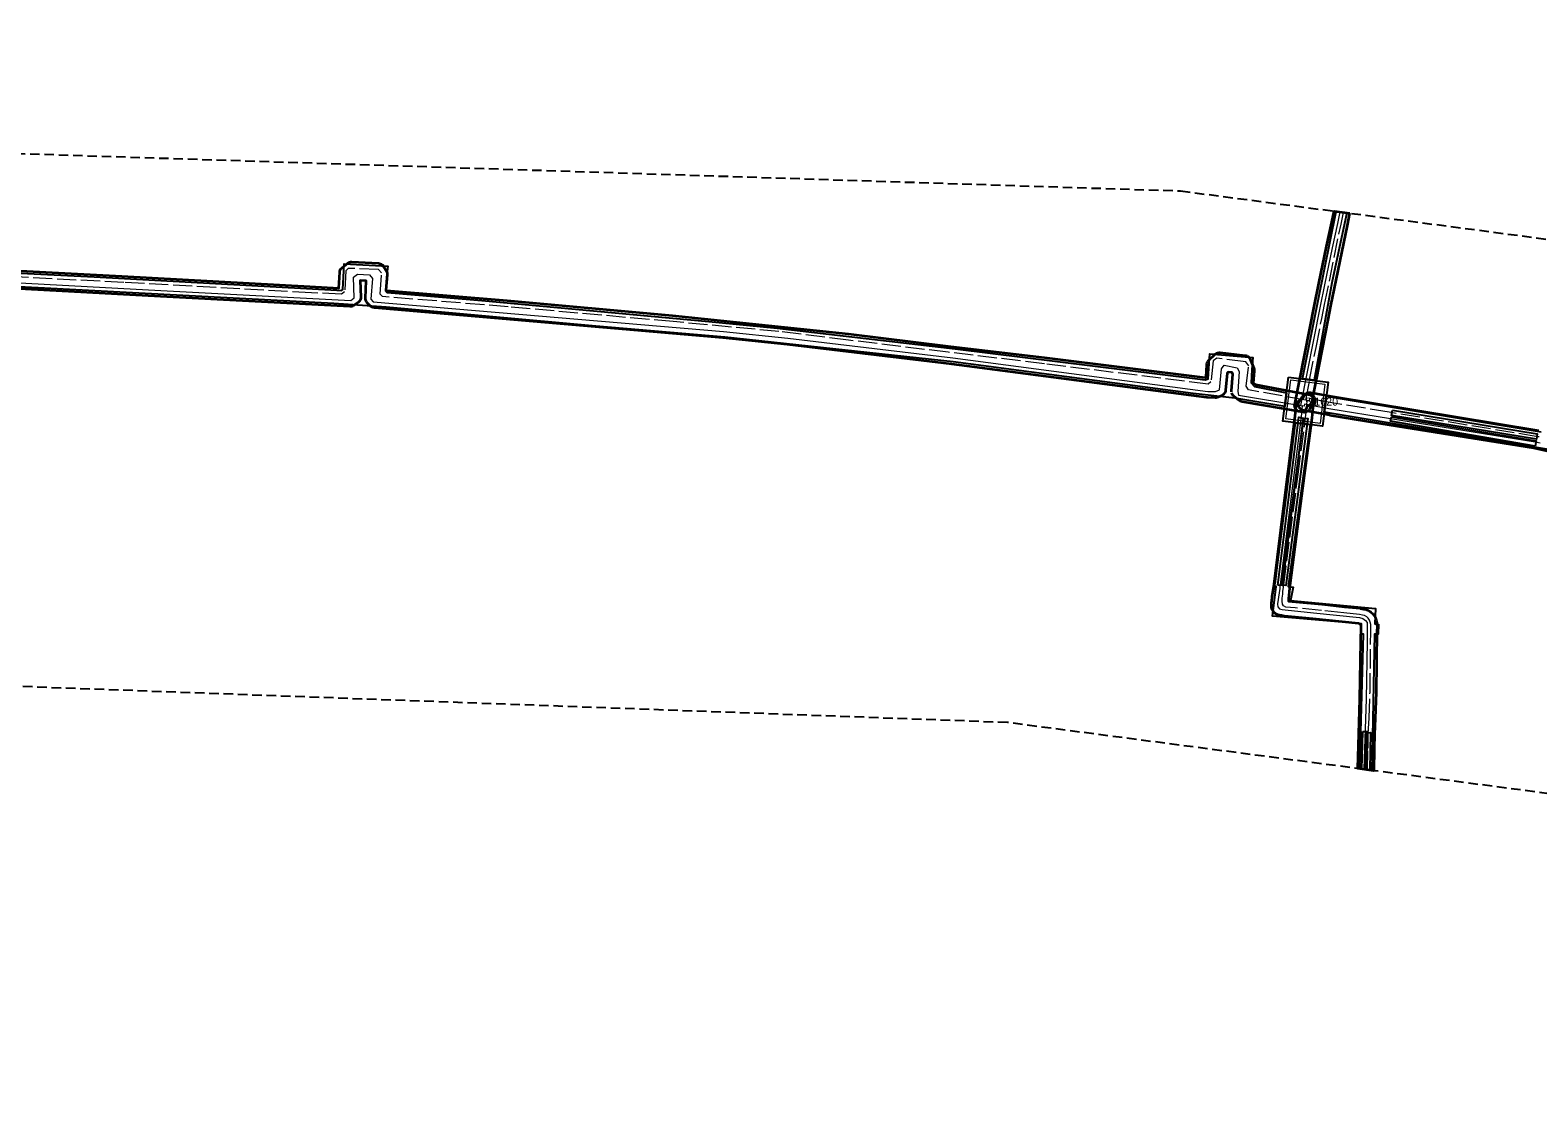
# Model space of a CAD drawing. Extents: x -451331 to -449998, y -1101254 to -1101132.
# Drawn here: x -450896.6 to -450726.4, y -1101253.5 to -1101132.1 of the extents above; entities that cross this region are included whole.
import ezdxf

# ---------------------------------------------------------------- set-up
doc = ezdxf.new("R2010")
doc.units = 0
doc.header["$LTSCALE"] = 0.36
doc.linetypes.add('LONG_DASHED', pattern=[7.5, 6, -1.5])
doc.linetypes.add('MEDIUM_DASHED', pattern=[4.5, 3, -1.5])
for name, color, linetype, lineweight in [('2', 7, 'Continuous', 13), ('3', 7, 'Continuous', 25), ('62', 7, 'MEDIUM_DASHED', 25), ('8', 7, 'Continuous', 35)]:
    doc.layers.add(name, color=color, linetype=linetype, lineweight=lineweight)

msp = doc.modelspace()

# ---------------------------------------------------------------- linework, layer by layer
at = {"layer": '2'}
for p, q in [((-450753.15, -1101174.471), (-450752.998, -1101174.497)), ((-450752.998, -1101174.497), (-450753.031, -1101174.872))]:
    msp.add_line(p, q, dxfattribs=at)
at = {"layer": '2', "linetype": 'LONG_DASHED'}
for p, q in [((-450752.423, -1101173.895), (-450752.592, -1101173.863)), ((-450752.525, -1101174.935), (-450752.423, -1101173.895))]:
    msp.add_line(p, q, dxfattribs=at)
at = {"layer": '2'}
for points in [[(-450753.15, -1101174.471), (-450750.934, -1101163.236), (-450750.445, -1101160.824), (-450749.565, -1101156.672), (-450748.981, -1101153.912), (-450748.706, -1101152.614)], [(-450924.057, -1101159.279), (-450903.363, -1101160.303), (-450881.853, -1101161.467), (-450860.382, -1101162.6), (-450860.033, -1101162.303), (-450860.078, -1101159.959), (-450859.628, -1101159.641), (-450858.305, -1101159.721), (-450857.961, -1101160.144), (-450858.14, -1101162.461), (-450857.872, -1101162.774), (-450818.326, -1101166.124), (-450811.077, -1101166.864), (-450792.45, -1101169.087), (-450763.663, -1101172.871), (-450762.79, -1101172.897), (-450762.34, -1101172.685), (-450762.092, -1101170.332), (-450761.805, -1101169.929), (-450760.353, -1101170.217), (-450760.111, -1101170.64), (-450760.277, -1101172.871), (-450760.195, -1101173.307), (-450753.15, -1101174.471)], [(-450751.662, -1101174.525), (-450752.719, -1101174.326), (-450752.759, -1101174.538), (-450752.998, -1101174.497)], [(-450743.258, -1101175.937), (-450749.764, -1101174.882), (-450751.662, -1101174.525)], [(-450753.031, -1101174.872), (-450753.109, -1101175.739), (-450754.306, -1101185.283), (-450755.523, -1101195.021), (-450755.539, -1101195.131)], [(-450726.139, -1101178.724), (-450726.711, -1101178.593), (-450743.025, -1101175.975), (-450743.258, -1101175.937)], [(-450755.539, -1101195.131), (-450755.676, -1101196.103), (-450755.747, -1101196.64), (-450755.77, -1101196.828), (-450755.779, -1101196.904), (-450755.75, -1101197.206), (-450755.564, -1101197.401), (-450755.252, -1101197.482), (-450754.92, -1101197.53), (-450751.724, -1101197.847), (-450746.515, -1101198.388), (-450746.149, -1101198.489), (-450745.85, -1101198.719), (-450745.679, -1101198.974), (-450745.652, -1101199.342), (-450745.665, -1101201.104), (-450745.793, -1101207.618), (-450746.031, -1101215.475), (-450746.033, -1101215.534)]]:
    msp.add_lwpolyline(points, dxfattribs=at)
at = {"layer": '2', "linetype": 'LONG_DASHED'}
for points in [[(-450752.592, -1101173.863), (-450752.159, -1101171.57), (-450751.439, -1101167.92), (-450750.79, -1101164.651), (-450750.475, -1101163.06), (-450748.616, -1101153.991), (-450748.342, -1101152.662)], [(-450752.592, -1101173.863), (-450759.07, -1101172.694), (-450759.306, -1101172.278), (-450759.032, -1101169.987), (-450759.348, -1101169.53), (-450762.651, -1101169.124), (-450763.042, -1101169.404), (-450763.299, -1101171.785), (-450763.608, -1101172.059), (-450782.098, -1101169.752), (-450792.952, -1101168.457), (-450804.201, -1101167.083), (-450812.061, -1101166.116), (-450824.006, -1101164.996), (-450842.623, -1101163.331), (-450856.817, -1101162.159), (-450857.095, -1101161.912), (-450856.925, -1101159.487), (-450857.263, -1101159.122), (-450860.682, -1101158.982), (-450860.942, -1101159.256), (-450861.094, -1101161.634), (-450861.434, -1101161.878), (-450864.831, -1101161.745), (-450886.009, -1101160.581), (-450908.217, -1101159.417)], [(-450751.502, -1101173.81), (-450752.176, -1101173.684), (-450752.222, -1101173.932), (-450752.423, -1101173.895)], [(-450743.19, -1101175.218), (-450749.661, -1101174.151), (-450751.502, -1101173.81)], [(-450755.2, -1101195.751), (-450755.166, -1101195.429), (-450755.119, -1101194.989), (-450755.104, -1101194.887), (-450755.085, -1101194.714), (-450754.355, -1101189.171), (-450753.46, -1101182.262), (-450752.609, -1101175.8), (-450752.525, -1101174.935)], [(-450726.252, -1101177.991), (-450726.397, -1101177.987), (-450743.19, -1101175.218)], [(-450745.615, -1101215.589), (-450745.566, -1101213.148), (-450745.534, -1101211.568), (-450745.455, -1101209.718), (-450745.338, -1101206.831), (-450745.252, -1101199.929), (-450745.251, -1101199.439), (-450745.259, -1101199.171), (-450745.311, -1101198.905), (-450745.389, -1101198.681), (-450745.549, -1101198.469), (-450745.714, -1101198.317), (-450745.957, -1101198.177), (-450746.175, -1101198.12), (-450746.539, -1101198.05), (-450748.287, -1101197.867), (-450750.83, -1101197.601), (-450753.794, -1101197.316), (-450754.862, -1101197.22), (-450755.111, -1101197.087), (-450755.227, -1101196.903), (-450755.259, -1101196.552), (-450755.25, -1101196.219), (-450755.2, -1101195.751)]]:
    msp.add_lwpolyline(points, dxfattribs=at)
at = {"layer": '3'}
for points in [[(-450747.966, -1101152.711), (-450748.225, -1101153.935), (-450749.637, -1101160.606), (-450751.632, -1101171.619), (-450752.975, -1101171.449), (-450751.159, -1101162.425), (-450749.178, -1101152.551)], [(-450754.549, -1101171.254), (-450750.083, -1101171.813), (-450750.706, -1101176.787), (-450755.173, -1101176.227)], [(-450744.38, -1101199.152), (-450744.409, -1101200.265), (-450744.853, -1101200.289), (-450745.146, -1101215.65), (-450746.492, -1101215.474), (-450746.079, -1101200.26), (-450746.364, -1101200.26), (-450746.32, -1101199.109), (-450756.345, -1101198.25), (-450755.95, -1101194.879), (-450756.109, -1101194.839), (-450756.014, -1101194.327), (-450755.778, -1101192.463), (-450754.85, -1101185.134), (-450753.744, -1101176.406), (-450752.112, -1101176.611), (-450754.586, -1101194.911), (-450754, -1101194.969), (-450754.301, -1101196.49), (-450744.719, -1101197.359), (-450744.799, -1101199.091)], [(-450755.739, -1101194.731), (-450753.371, -1101175.798), (-450752.873, -1101175.874), (-450755.25, -1101194.789)], [(-450752.814, -1101175.879), (-450752.375, -1101175.945), (-450754.839, -1101194.772), (-450755.34, -1101194.719)], [(-450742.933, -1101175.755), (-450726.603, -1101178.438), (-450726.683, -1101179.04), (-450743.012, -1101176.236)], [(-450742.812, -1101174.995), (-450726.461, -1101177.654), (-450726.559, -1101178.259), (-450742.91, -1101175.6)], [(-450746.15, -1101211.252), (-450745.65, -1101211.258), (-450745.782, -1101215.567), (-450746.28, -1101215.502)], [(-450745.863, -1101215.556), (-450745.78, -1101211.403), (-450745.28, -1101211.383), (-450745.365, -1101215.622)]]:
    msp.add_lwpolyline(points, close=True, dxfattribs=at)
for points in [[(-450920.932, -1101158.346), (-450889.362, -1101159.955), (-450861.956, -1101161.444), (-450861.45, -1101161.471), (-450861.284, -1101161.373), (-450861.177, -1101159.248), (-450861.151, -1101158.461), (-450856.236, -1101158.719), (-450856.316, -1101159.584), (-450856.482, -1101161.485), (-450856.287, -1101161.707), (-450845.59, -1101162.629), (-450819.971, -1101164.969), (-450812.261, -1101165.721), (-450792.175, -1101168.053), (-450765.116, -1101171.407), (-450763.968, -1101171.55), (-450763.613, -1101171.436), (-450763.501, -1101169.732), (-450763.41, -1101168.617), (-450758.56, -1101169.061), (-450758.668, -1101170.383), (-450758.673, -1101170.45), (-450758.769, -1101171.907), (-450758.374, -1101172.311), (-450754.772, -1101173.03), (-450754.966, -1101174.575), (-450760.596, -1101173.648), (-450765.31, -1101173.108), (-450792.408, -1101169.546), (-450818.178, -1101166.758), (-450832.744, -1101165.501), (-450856.404, -1101163.358), (-450862.309, -1101162.958), (-450895.688, -1101161.169), (-450923.154, -1101159.774)], [(-450724.513, -1101179.55), (-450750.507, -1101175.197), (-450750.285, -1101173.424), (-450726.039, -1101177.429)]]:
    msp.add_lwpolyline(points, dxfattribs=at)
at = {"layer": '3', "lineweight": 13}
msp.add_lwpolyline([(-450754.284, -1101171.573), (-450750.442, -1101172.049), (-450750.974, -1101176.494), (-450754.839, -1101175.97)], close=True, dxfattribs=at)
at = {"layer": '62'}
msp.add_lwpolyline([(-450786.261, -1101210.25), (-451322.174, -1101190.711), (-451330.547, -1101132.096), (-450766.722, -1101150.239), (-450459.689, -1101190.711), (-449997.743, -1101194.898), (-449997.743, -1101249.327), (-450456.897, -1101253.514)], close=True, dxfattribs=at)
at = {"layer": '8'}
msp.add_lwpolyline([(-450747.646, -1101152.753), (-450747.93, -1101154.132), (-450749.788, -1101163.199), (-450750.104, -1101164.787), (-450750.752, -1101168.056), (-450751.472, -1101171.702), (-450751.904, -1101173.993), (-450751.936, -1101174.107), (-450751.986, -1101174.214), (-450752.054, -1101174.311), (-450752.137, -1101174.395), (-450752.232, -1101174.464), (-450752.338, -1101174.516), (-450752.452, -1101174.549), (-450752.463, -1101174.606), (-450752.497, -1101174.723), (-450752.551, -1101174.833), (-450752.623, -1101174.931), (-450752.711, -1101175.016), (-450752.812, -1101175.084), (-450752.924, -1101175.133), (-450753.042, -1101175.162), (-450753.164, -1101175.171), (-450753.285, -1101175.157), (-450753.402, -1101175.123), (-450753.512, -1101175.07), (-450753.61, -1101174.998), (-450753.695, -1101174.91), (-450753.763, -1101174.808), (-450753.812, -1101174.697), (-450753.841, -1101174.578), (-450753.85, -1101174.456), (-450753.836, -1101174.335), (-450751.62, -1101163.099), (-450751.131, -1101160.686), (-450751.13, -1101160.679), (-450750.25, -1101156.527), (-450749.666, -1101153.767), (-450749.402, -1101152.522)], close=True, dxfattribs=at)
for points in [[(-450908.487, -1101158.702), (-450886.233, -1101159.866), (-450865.014, -1101161.03)], [(-450865.014, -1101161.03), (-450861.737, -1101161.202), (-450861.649, -1101159.418), (-450861.633, -1101159.3), (-450861.597, -1101159.187), (-450861.543, -1101159.082), (-450861.471, -1101158.987), (-450861.385, -1101158.905), (-450860.748, -1101158.402), (-450860.665, -1101158.345), (-450860.574, -1101158.301), (-450860.478, -1101158.271), (-450860.379, -1101158.254), (-450860.278, -1101158.252), (-450857.262, -1101158.411), (-450857.147, -1101158.427), (-450857.035, -1101158.462), (-450856.932, -1101158.514), (-450856.838, -1101158.583), (-450856.757, -1101158.667), (-450856.691, -1101158.763), (-450856.373, -1101159.318), (-450856.328, -1101159.414), (-450856.298, -1101159.516), (-450856.283, -1101159.621), (-450856.284, -1101159.727), (-450856.433, -1101161.43), (-450856.373, -1101161.47), (-450842.739, -1101162.62), (-450824.084, -1101164.287), (-450824.073, -1101164.288), (-450804.229, -1101166.378), (-450804.218, -1101166.379), (-450792.948, -1101167.755), (-450782.072, -1101169.052), (-450763.939, -1101171.302), (-450763.841, -1101171.255), (-450763.78, -1101169.874), (-450763.767, -1101169.769), (-450763.739, -1101169.667), (-450763.695, -1101169.57), (-450763.638, -1101169.482), (-450763.568, -1101169.402), (-450762.825, -1101168.687), (-450762.747, -1101168.621), (-450762.659, -1101168.568), (-450762.565, -1101168.528), (-450762.466, -1101168.502), (-450762.364, -1101168.491), (-450762.262, -1101168.495), (-450759.431, -1101168.813), (-450759.324, -1101168.833), (-450759.222, -1101168.87), (-450759.127, -1101168.921), (-450759.042, -1101168.987), (-450758.967, -1101169.065), (-450758.905, -1101169.154), (-450758.858, -1101169.251), (-450758.461, -1101170.257), (-450758.429, -1101170.36), (-450758.413, -1101170.467), (-450758.414, -1101170.575), (-450758.534, -1101171.933), (-450758.255, -1101172.097), (-450752.093, -1101173.244), (-450751.978, -1101173.276), (-450751.869, -1101173.328), (-450751.771, -1101173.397), (-450751.686, -1101173.481), (-450751.617, -1101173.579), (-450751.566, -1101173.688), (-450751.534, -1101173.803), (-450751.521, -1101173.922), (-450751.53, -1101174.042), (-450751.559, -1101174.158), (-450751.607, -1101174.268), (-450751.673, -1101174.368), (-450751.756, -1101174.455), (-450751.852, -1101174.527), (-450751.958, -1101174.581), (-450752.073, -1101174.616), (-450752.095, -1101174.728), (-450752.135, -1101174.833), (-450752.191, -1101174.932), (-450752.262, -1101175.02), (-450752.346, -1101175.095), (-450752.442, -1101175.156), (-450752.546, -1101175.2), (-450752.656, -1101175.227), (-450752.768, -1101175.236), (-450752.881, -1101175.227), (-450759.787, -1101174.037), (-450759.898, -1101174.008), (-450760.003, -1101173.961), (-450760.099, -1101173.898), (-450760.708, -1101173.421), (-450760.792, -1101173.344), (-450760.862, -1101173.254), (-450760.917, -1101173.153), (-450760.954, -1101173.045)], [(-450760.974, -1101172.932), (-450760.975, -1101172.818), (-450760.83, -1101170.92), (-450760.919, -1101170.743), (-450761.349, -1101170.692), (-450761.481, -1101170.806), (-450761.643, -1101172.743), (-450761.659, -1101172.847), (-450761.691, -1101172.947), (-450761.737, -1101173.041), (-450761.797, -1101173.127), (-450761.869, -1101173.203), (-450761.951, -1101173.267), (-450762.042, -1101173.319), (-450762.492, -1101173.53), (-450762.594, -1101173.569), (-450762.701, -1101173.591), (-450762.81, -1101173.597), (-450763.684, -1101173.57), (-450763.754, -1101173.565), (-450792.537, -1101169.782), (-450811.154, -1101167.56), (-450818.392, -1101166.821), (-450857.73, -1101163.434), (-450857.826, -1101163.419), (-450857.92, -1101163.391), (-450858.009, -1101163.349), (-450858.091, -1101163.296), (-450858.165, -1101163.232), (-450858.535, -1101162.862), (-450858.609, -1101162.774), (-450858.668, -1101162.675), (-450858.711, -1101162.569), (-450858.734, -1101162.456), (-450858.74, -1101162.342), (-450858.67, -1101160.4), (-450859.358, -1101160.359), (-450859.272, -1101162.229), (-450859.277, -1101162.347), (-450859.302, -1101162.463), (-450859.345, -1101162.573), (-450859.407, -1101162.674), (-450859.485, -1101162.764), (-450859.576, -1101162.839), (-450860.079, -1101163.182), (-450860.178, -1101163.239), (-450860.285, -1101163.279), (-450860.398, -1101163.3), (-450860.512, -1101163.304), (-450881.89, -1101162.166), (-450903.4, -1101161.002)], [(-450724.649, -1101179.781), (-450726.844, -1101179.281), (-450743.137, -1101176.666), (-450749.876, -1101175.573), (-450749.893, -1101175.57), (-450752.848, -1101175.014), (-450752.964, -1101174.982), (-450753.071, -1101174.932), (-450753.169, -1101174.863), (-450753.254, -1101174.779), (-450753.323, -1101174.681), (-450753.374, -1101174.574), (-450753.407, -1101174.459), (-450753.419, -1101174.34), (-450753.412, -1101174.221), (-450753.384, -1101174.105), (-450753.336, -1101173.995), (-450753.271, -1101173.895), (-450753.19, -1101173.808), (-450753.095, -1101173.736), (-450752.989, -1101173.68), (-450752.875, -1101173.644), (-450752.858, -1101173.526), (-450752.822, -1101173.414), (-450752.767, -1101173.309), (-450752.695, -1101173.214), (-450752.608, -1101173.133), (-450752.509, -1101173.068), (-450752.4, -1101173.021), (-450752.285, -1101172.993), (-450752.167, -1101172.984), (-450752.049, -1101172.996), (-450749.54, -1101173.462), (-450726.33, -1101177.289)], [(-450746.731, -1101215.442), (-450746.493, -1101207.6), (-450746.365, -1101201.094), (-450746.352, -1101199.366), (-450746.364, -1101199.21), (-450746.367, -1101199.205), (-450746.468, -1101199.127), (-450746.646, -1101199.078), (-450751.794, -1101198.544), (-450754.989, -1101198.226), (-450755.012, -1101198.223), (-450755.019, -1101198.223), (-450755.351, -1101198.175), (-450755.418, -1101198.162), (-450755.428, -1101198.159), (-450755.74, -1101198.079), (-450755.832, -1101198.048), (-450755.918, -1101198.005), (-450755.998, -1101197.95), (-450756.07, -1101197.885), (-450756.256, -1101197.69), (-450756.329, -1101197.599), (-450756.386, -1101197.498), (-450756.426, -1101197.388), (-450756.447, -1101197.273), (-450756.476, -1101196.97), (-450756.479, -1101196.894), (-450756.474, -1101196.818), (-450756.464, -1101196.743), (-450756.441, -1101196.555), (-450756.441, -1101196.548), (-450756.37, -1101196.011), (-450756.369, -1101196.005), (-450756.217, -1101194.929), (-450755.001, -1101185.196), (-450753.806, -1101175.664), (-450753.695, -1101174.434), (-450753.675, -1101174.321), (-450753.637, -1101174.213), (-450753.583, -1101174.113), (-450753.512, -1101174.023), (-450753.428, -1101173.945), (-450753.333, -1101173.882), (-450753.228, -1101173.836), (-450753.117, -1101173.807), (-450753.092, -1101173.689), (-450753.046, -1101173.577), (-450752.982, -1101173.475), (-450752.901, -1101173.385), (-450752.806, -1101173.31), (-450752.7, -1101173.253), (-450752.585, -1101173.215), (-450752.466, -1101173.197), (-450752.345, -1101173.2), (-450752.226, -1101173.224), (-450752.114, -1101173.268), (-450752.01, -1101173.33), (-450751.919, -1101173.41), (-450751.843, -1101173.503), (-450751.784, -1101173.609), (-450751.744, -1101173.723), (-450751.725, -1101173.842), (-450751.726, -1101173.963), (-450751.913, -1101175.868), (-450751.913, -1101175.874), (-450751.916, -1101175.891), (-450752.766, -1101182.353), (-450753.661, -1101189.261), (-450754.39, -1101194.798), (-450754.408, -1101194.964), (-450754.412, -1101194.994), (-450754.425, -1101195.079), (-450754.47, -1101195.503), (-450754.55, -1101196.266), (-450754.558, -1101196.53), (-450754.556, -1101196.545), (-450753.73, -1101196.619), (-450750.763, -1101196.905), (-450750.757, -1101196.905), (-450748.215, -1101197.171), (-450746.467, -1101197.353), (-450746.408, -1101197.362), (-450746.041, -1101197.433), (-450746.001, -1101197.443), (-450745.782, -1101197.499), (-450745.692, -1101197.529), (-450745.607, -1101197.57), (-450745.364, -1101197.711), (-450745.298, -1101197.754), (-450745.237, -1101197.804), (-450745.073, -1101197.957), (-450745.035, -1101197.995), (-450744.992, -1101198.046), (-450744.832, -1101198.258), (-450744.772, -1101198.35), (-450744.728, -1101198.451), (-450744.65, -1101198.675), (-450744.624, -1101198.77), (-450744.572, -1101199.036), (-450744.563, -1101199.096)], [(-450744.56, -1101199.15), (-450744.552, -1101199.418), (-450744.551, -1101199.44), (-450744.553, -1101199.931), (-450744.553, -1101199.938), (-450744.638, -1101206.84), (-450744.639, -1101206.859), (-450744.756, -1101209.747), (-450744.834, -1101211.589), (-450744.866, -1101213.163), (-450744.917, -1101215.681), (-450746.731, -1101215.442)]]:
    msp.add_lwpolyline(points, dxfattribs=at)

# ---------------------------------------------------------------- texts
at = {"layer": '3'}
msp.add_text('5/1620 ', height=0.9, dxfattribs=at).set_placement((-450752.632, -1101174.474))

doc.saveas('drawing.dxf')
